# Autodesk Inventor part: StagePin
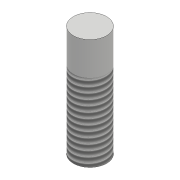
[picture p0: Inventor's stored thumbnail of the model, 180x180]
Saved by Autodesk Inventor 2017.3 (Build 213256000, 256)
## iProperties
Part Number: StagePin
Material: 一般
Document SubType Name: Modeling
Designer: kyushu-hep
Density: 1 g/cm^3
Appearance: 既定
Author: kyushu-hep
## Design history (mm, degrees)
sketch "スケッチ1"
  geometry: C1 r 1.5 at (0, 0); 1 further point
  constraints: 1 centre point, 1 coincident
  dimensions: "d0" = 3 diameter of C1
extrude "押し出し1" new body sketch "スケッチ1" distance "d1" = 10; taper "d2" = 0 deg
feature "ねじ1" dims "d3" = 7, "d4" = 0
node "ソリッド1"
